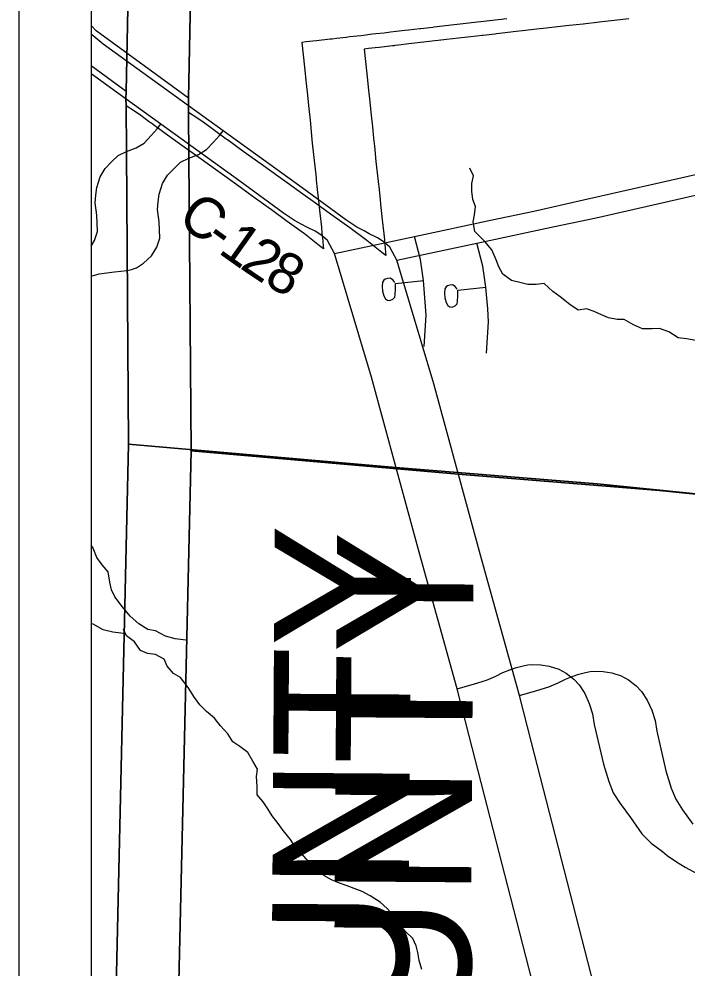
# Model space of a CAD drawing. Extents: x -38.2 to 41.9, y -4 to 24.9.
# Drawn here: x 2 to 2.926, y 15.94 to 17.256 of the extents above; entities that cross this region are included whole.
import ezdxf

# ---------------------------------------------------------------- set-up
doc = ezdxf.new("R2010")
doc.units = 0
for name, color, linetype in [('Default', 7, 'Continuous'), ('GM_X_City_Street', 7, 'Continuous'), ('GM_X_County_Road', 7, 'Continuous'), ('GM_X_County_Road_Text', 7, 'Continuous'), ('GM_X_County_Text', 7, 'Continuous'), ('GM_X_Interchange_Ramps', 7, 'Continuous'), ('GM_X_Interstate_Location', 7, 'Continuous'), ('GM_X_Minor_River', 7, 'Continuous'), ('GM_X_Minor_River_Text', 7, 'Continuous'), ('GM_X_Township_Road_Text', 7, 'Continuous'), ('Level 38', 7, 'Continuous'), ('SH_Cut_Line', 7, 'Continuous'), ('SH_Data', 7, 'Continuous')]:
    doc.layers.add(name, color=color, linetype=linetype)

msp = doc.modelspace()

# ---------------------------------------------------------------- linework, layer by layer
at = {"layer": 'Default'}
msp.add_lwpolyline([(2.6765, 17.2561), (2.6404, 17.252), (2.6356, 17.2515), (2.6158, 17.2492), (2.5991, 17.2473), (2.5955, 17.2469), (2.5756, 17.2446), (2.574, 17.2444), (2.5571, 17.2424), (2.5559, 17.2423), (2.5402, 17.2405), (2.5353, 17.2399), (2.5232, 17.2385), (2.5152, 17.2376), (2.5063, 17.2366), (2.4948, 17.2353), (2.4903, 17.2348), (2.4743, 17.2329), (2.4583, 17.2311), (2.4542, 17.2306), (2.4539, 17.2306), (2.4401, 17.229), (2.4345, 17.2283), (2.4334, 17.2282), (2.4327, 17.2281), (2.4315, 17.228), (2.4128, 17.2258), (2.4074, 17.2252), (2.3982, 17.2242), (2.3923, 17.2235), (2.396, 17.1891), (2.3984, 17.1665), (2.4001, 17.1506), (2.4002, 17.1501), (2.402, 17.1319), (2.4036, 17.1159), (2.4052, 17.0998), (2.4063, 17.0888), (2.4068, 17.0838), (2.4085, 17.0678), (2.4103, 17.0518), (2.412, 17.0358), (2.4123, 17.0328), (2.4137, 17.0198), (2.4154, 17.0038), (2.4172, 16.9868), (2.4193, 16.9672), (2.4202, 16.9589), (2.4206, 16.955), (2.4207, 16.9537), (2.4215, 16.9468), (2.4225, 16.9373), (2.4167, 16.9417), (2.3959, 16.9583), (2.3721, 16.9755), (2.3504, 16.9913), (2.3456, 16.9948), (2.3248, 17.0097), (2.3072, 17.0224), (2.2854, 17.0381), (2.2723, 17.0474), (2.2525, 17.0617), (2.226, 17.0806), (2.2025, 17.0975), (2.201, 17.0986), (2.1827, 17.112), (2.1827, 17.112), (2.1809, 17.1132), (2.1688, 17.1221), (2.1604, 17.1282), (2.1485, 17.1357), (2.1486, 17.1556), (2.1, 17.1909), (2.1, 14.1)], dxfattribs=at)
at = {"layer": 'GM_X_City_Street'}
for points in [[(2.1492, 17.0725), (2.1623, 17.0773), (2.1735, 17.0841), (2.1834, 17.0945), (2.1917, 17.1039), (2.193, 17.1055), (2.1967, 17.1103)], [(2.1, 16.9412), (2.1046, 16.9489), (2.1089, 16.9615), (2.1078, 16.9841), (2.1057, 17.001), (2.1064, 17.0118), (2.1078, 17.0224), (2.1127, 17.0371), (2.1194, 17.0487), (2.1285, 17.0581), (2.1376, 17.0669), (2.1492, 17.0725)], [(2.562, 16.8021), (2.5647, 16.8455), (2.5635, 16.8635), (2.5608, 16.8936), (2.5569, 16.9225), (2.5486, 16.9543)], [(2.5213, 16.8908), (2.5184, 16.8943), (2.5147, 16.8965), (2.5111, 16.8962), (2.5078, 16.8952), (2.5059, 16.894), (2.504, 16.8913), (2.5035, 16.8851), (2.5041, 16.8788), (2.5061, 16.872), (2.5084, 16.8679), (2.5111, 16.8662), (2.5141, 16.8659), (2.5186, 16.8674), (2.521, 16.8703), (2.5218, 16.874), (2.5219, 16.8814), (2.5219, 16.8893), (2.5608, 16.8936)], [(2.6075, 16.3273), (2.6319, 16.3342), (2.6483, 16.3394), (2.6613, 16.3448), (2.6712, 16.3497), (2.6806, 16.3537), (2.69, 16.3568), (2.6993, 16.3593), (2.7055, 16.3604), (2.7114, 16.361), (2.7238, 16.3606), (2.7354, 16.3587), (2.7487, 16.3544), (2.7587, 16.3491), (2.7696, 16.3406), (2.7766, 16.3328), (2.7846, 16.3208), (2.7909, 16.3068), (2.7955, 16.2925), (2.7978, 16.278), (2.8107, 16.223), (2.818, 16.1989), (2.8242, 16.1833), (2.8336, 16.1685), (2.8478, 16.1488), (2.8637, 16.1264), (2.8769, 16.1131), (2.8923, 16.1017), (2.8987, 16.0961), (2.912, 16.0875), (2.9238, 16.0801), (2.958, 16.0613)]]:
    msp.add_lwpolyline(points, dxfattribs=at)
at = {"layer": 'GM_X_County_Road'}
msp.add_line((2.1487, 17.145), (2.1, 17.18), dxfattribs=at)
for points in [[(2.8455, 17.2562), (2.8252, 17.2538), (2.8131, 17.2524), (2.8049, 17.2515), (2.7823, 17.2491), (2.763, 17.2469), (2.7269, 17.2428), (2.722, 17.2423), (2.7022, 17.24), (2.6855, 17.2381), (2.682, 17.2377), (2.662, 17.2354), (2.6605, 17.2352), (2.6436, 17.2333), (2.6424, 17.2331), (2.6266, 17.2313), (2.6218, 17.2307), (2.6097, 17.2294), (2.6017, 17.2284), (2.5928, 17.2274), (2.5813, 17.2261), (2.5768, 17.2256), (2.5608, 17.2237), (2.5448, 17.2219), (2.5407, 17.2214), (2.5404, 17.2214), (2.5265, 17.2198), (2.521, 17.2192), (2.5199, 17.219), (2.5191, 17.2189), (2.518, 17.2188), (2.4993, 17.2167), (2.4939, 17.216), (2.4847, 17.215), (2.4788, 17.2143), (2.4825, 17.1799), (2.4849, 17.1573), (2.4866, 17.1414), (2.4867, 17.1409), (2.4885, 17.1227), (2.4901, 17.1067), (2.4917, 17.0906), (2.4928, 17.0796), (2.4933, 17.0746), (2.495, 17.0586), (2.4967, 17.0426), (2.4985, 17.0266), (2.4988, 17.0236), (2.5002, 17.0106), (2.5019, 16.9946), (2.5037, 16.9776), (2.5058, 16.9581), (2.5067, 16.9497), (2.5071, 16.9458), (2.5072, 16.9445), (2.5079, 16.9376), (2.5089, 16.9281), (2.5032, 16.9325), (2.4824, 16.9491), (2.4586, 16.9663), (2.4368, 16.9821), (2.4321, 16.9856), (2.4113, 17.0005), (2.3937, 17.0132), (2.3718, 17.0289), (2.3588, 17.0382), (2.3389, 17.0525), (2.3125, 17.0715), (2.289, 17.0883), (2.2874, 17.0894), (2.2692, 17.1028), (2.2692, 17.1028), (2.2674, 17.1041), (2.2553, 17.1129), (2.2468, 17.119), (2.235, 17.1266), (2.2351, 17.1464), (2.1069, 17.2395), (2.1, 17.2471), (2.1, 14.1)], [(2.4207, 16.9551), (2.42, 16.9557), (2.4109, 16.9618), (2.3993, 16.9675), (2.3921, 16.9713), (2.3821, 16.9766), (2.3667, 16.987), (2.3064, 17.0312), (2.1967, 17.1103), (2.1487, 17.145)], [(2.4376, 16.9307), (2.5486, 16.9543), (2.6562, 16.9777), (2.7139, 16.9895), (2.7828, 17.0054), (2.9953, 17.0536), (3.0911, 17.077), (3.0948, 17.0781)], [(2.4376, 16.9307), (2.4278, 16.9487), (2.4207, 16.9551)], [(2.523, 16.6337), (2.4888, 16.7592), (2.4376, 16.9307)], [(2.8235, 15.1398), (2.8339, 15.2041), (2.8358, 15.2222), (2.8341, 15.2358), (2.8313, 15.2481), (2.7757, 15.4503), (2.7392, 15.5699), (2.7209, 15.6326), (2.7183, 15.6447), (2.7166, 15.6563), (2.7158, 15.6686), (2.7163, 15.6779), (2.7246, 15.7195), (2.7319, 15.7477), (2.7392, 15.7855), (2.7397, 15.7991), (2.7385, 15.818), (2.7355, 15.8321), (2.7196, 15.8918), (2.6244, 16.262), (2.6075, 16.3273), (2.5551, 16.5169), (2.523, 16.6337)]]:
    msp.add_lwpolyline(points, dxfattribs=at)
at = {"layer": 'GM_X_Interchange_Ramps'}
for points in [[(2.1, 20.4515), (2.1, 14.1636), (2.1303, 14.1626), (2.1303, 14.1722), (2.1335, 15.4167), (2.1334, 15.4951), (2.1328, 15.831), (2.1521, 16.6664), (2.1489, 17.073), (2.1485, 17.1357), (2.1484, 17.1455), (2.1486, 17.1556), (2.1569, 17.5704), (2.1549, 17.5972), (2.1521, 17.6416), (2.1422, 17.7563), (2.1427, 17.838), (2.1429, 18.1709), (2.1421, 18.2952), (2.138, 18.8976), (2.1339, 19.396), (2.1223, 20.2725), (2.1124, 20.4526)], [(2.1, 20.4344), (2.1, 14.1575), (2.2168, 14.1534), (2.2168, 14.163), (2.22, 15.4075), (2.2199, 15.4859), (2.2193, 15.8218), (2.2386, 16.6572), (2.2354, 17.0638), (2.235, 17.1266), (2.2349, 17.1363), (2.2351, 17.1464), (2.2434, 17.5612), (2.2414, 17.5881), (2.2386, 17.6324), (2.2287, 17.7471), (2.2291, 17.8288), (2.2294, 18.1617), (2.2286, 18.286), (2.2245, 18.8884), (2.2204, 19.3868), (2.2088, 20.2633), (2.1989, 20.4434)]]:
    msp.add_lwpolyline(points, close=True, dxfattribs=at)
for points in [[(2.1569, 17.5704), (2.1486, 17.1556), (2.1484, 17.1455), (2.1485, 17.1357), (2.1489, 17.073), (2.1521, 16.6664), (2.5228, 16.6342), (2.8019, 16.6115), (3.0621, 16.5852), (3.1389, 16.5821), (3.471, 16.5538), (3.8743, 16.4969), (3.8908, 16.5049), (3.9086, 16.5077), (3.9238, 16.5054), (3.9778, 16.5019), (4.1257, 16.4908), (4.1951, 16.4857), (4.2738, 16.48), (4.4315, 16.4679)], [(2.2434, 17.5612), (2.2351, 17.1464), (2.2349, 17.1363), (2.235, 17.1266), (2.2354, 17.0638), (2.2386, 16.6572), (2.6092, 16.625), (2.8884, 16.6024), (3.1485, 16.5761), (3.2254, 16.5729), (3.5575, 16.5447), (3.9608, 16.4877), (3.9773, 16.4958), (3.9951, 16.4985), (4.0103, 16.4962), (4.0643, 16.4927), (4.2121, 16.4816), (4.2816, 16.4765), (4.3603, 16.4708)], [(4.4315, 16.4679), (4.2738, 16.48), (4.1951, 16.4857), (4.1257, 16.4908), (3.9778, 16.5019), (3.9238, 16.5054), (3.9086, 16.5077), (3.8908, 16.5049), (3.8743, 16.4969), (3.471, 16.5538), (3.1389, 16.5821), (3.0621, 16.5852), (2.8019, 16.6115), (2.5228, 16.6342), (2.1521, 16.6664), (2.1328, 15.831), (2.1334, 15.4951), (2.1335, 15.4167), (2.1303, 14.1722), (2.1303, 14.1626), (2.1, 14.1636), (2.1, 14.1), (6.3126, 14.1)], [(4.3603, 16.4708), (4.2816, 16.4765), (4.2121, 16.4816), (4.0643, 16.4927), (4.0103, 16.4962), (3.9951, 16.4985), (3.9773, 16.4958), (3.9608, 16.4877), (3.5575, 16.5447), (3.2254, 16.5729), (3.1485, 16.5761), (2.8884, 16.6024), (2.6092, 16.625), (2.2386, 16.6572), (2.2193, 15.8218), (2.2199, 15.4859), (2.22, 15.4075), (2.2168, 14.163), (2.2168, 14.1534), (2.1, 14.1575), (2.1, 14.1), (6.3995, 14.1)]]:
    msp.add_lwpolyline(points, dxfattribs=at)
at = {"layer": 'GM_X_Interstate_Location'}
for points in [[(2.2356, 17.0633), (2.2488, 17.0682), (2.26, 17.0749), (2.2699, 17.0853), (2.2782, 17.0947), (2.2794, 17.0963), (2.2832, 17.1012)], [(2.1559, 16.9089), (2.1631, 16.911), (2.1725, 16.9176), (2.1838, 16.9275), (2.1911, 16.9397), (2.1953, 16.9523), (2.1943, 16.975), (2.1922, 16.9918), (2.1929, 17.0027), (2.1943, 17.0132), (2.1992, 17.0279), (2.2058, 17.0395), (2.215, 17.0489), (2.2241, 17.0577), (2.2356, 17.0633)], [(2.6485, 16.7929), (2.6512, 16.8363), (2.65, 16.8543), (2.6473, 16.8844), (2.6434, 16.9133), (2.6351, 16.9451)], [(2.1, 16.8994), (2.1112, 16.9029), (2.1326, 16.9054), (2.1498, 16.9071), (2.1559, 16.9089)], [(2.6078, 16.8816), (2.6049, 16.8851), (2.6012, 16.8873), (2.5976, 16.887), (2.5943, 16.886), (2.5924, 16.8848), (2.5905, 16.8821), (2.59, 16.8759), (2.5906, 16.8696), (2.5926, 16.8628), (2.5948, 16.8587), (2.5976, 16.857), (2.6006, 16.8567), (2.6051, 16.8583), (2.6075, 16.8611), (2.6083, 16.8649), (2.6084, 16.8722), (2.6084, 16.8801), (2.6473, 16.8844)], [(2.694, 16.3181), (2.7183, 16.325), (2.7348, 16.3302), (2.7478, 16.3356), (2.7577, 16.3405), (2.7671, 16.3445), (2.7765, 16.3476), (2.7858, 16.3501), (2.792, 16.3513), (2.7979, 16.3518), (2.8102, 16.3514), (2.8219, 16.3495), (2.8351, 16.3452), (2.8451, 16.3399), (2.856, 16.3314), (2.8631, 16.3236), (2.8711, 16.3116), (2.8774, 16.2976), (2.882, 16.2834), (2.8843, 16.2688), (2.8971, 16.2138), (2.9045, 16.1897), (2.9107, 16.1741), (2.9201, 16.1593), (2.9343, 16.1396)]]:
    msp.add_lwpolyline(points, dxfattribs=at)
at = {"layer": 'GM_X_Minor_River'}
for points in [[(2.9385, 16.8103), (2.9256, 16.8126), (2.9143, 16.8138), (2.901, 16.8225), (2.8881, 16.8267), (2.8782, 16.8264), (2.8646, 16.8264), (2.8524, 16.8322), (2.8391, 16.8394), (2.8293, 16.8395), (2.8175, 16.8418), (2.8077, 16.846), (2.7974, 16.8506), (2.7868, 16.854), (2.7754, 16.8521), (2.7637, 16.8601), (2.7504, 16.8708), (2.7402, 16.8781), (2.7281, 16.8891), (2.7174, 16.888), (2.7056, 16.888), (2.6962, 16.8903), (2.6829, 16.8934), (2.6708, 16.9022), (2.6655, 16.9125), (2.6617, 16.9223), (2.6557, 16.936), (2.6458, 16.9475), (2.6322, 16.9615), (2.63, 16.9748), (2.6319, 16.9843), (2.6331, 16.9961), (2.6293, 17.006), (2.6278, 17.0174), (2.6278, 17.028), (2.6305, 17.0386), (2.6252, 17.0493)], [(2.1448, 16.4039), (2.13, 16.4058), (2.1167, 16.4093), (2.1031, 16.4169), (2.1, 16.4174)], [(2.5587, 15.9382), (2.5548, 15.9505), (2.5532, 15.9616), (2.5508, 15.9711), (2.5461, 15.9811), (2.5361, 15.9909), (2.5273, 16.0014), (2.52, 16.0126), (2.5104, 16.0227), (2.5008, 16.0314), (2.4869, 16.0401), (2.4761, 16.0461), (2.4648, 16.0502), (2.4551, 16.0542), (2.4445, 16.0576), (2.4333, 16.0624), (2.4228, 16.0684), (2.4113, 16.0794), (2.4009, 16.0884), (2.3921, 16.0985), (2.3832, 16.1082), (2.3763, 16.1183), (2.3663, 16.1307), (2.3594, 16.1404), (2.3513, 16.1513), (2.3451, 16.1609), (2.3385, 16.1706), (2.3304, 16.1803), (2.3304, 16.1917), (2.3296, 16.2055), (2.3306, 16.2161), (2.3244, 16.2269), (2.3172, 16.2389), (2.3064, 16.2471), (2.2967, 16.2538), (2.2897, 16.2647), (2.2794, 16.276), (2.2713, 16.2868), (2.2602, 16.2959), (2.2506, 16.3049), (2.2436, 16.3153), (2.2345, 16.3289), (2.2242, 16.3428), (2.2145, 16.3484), (2.2057, 16.3589), (2.2014, 16.3685), (2.1894, 16.3749), (2.1784, 16.3763), (2.1687, 16.3804), (2.1602, 16.3924), (2.1491, 16.4007), (2.1448, 16.4098)]]:
    msp.add_lwpolyline(points, dxfattribs=at)
at = {"layer": 'GM_X_Minor_River_Text'}
msp.add_lwpolyline([(2.2312, 16.3947), (2.2165, 16.3966), (2.2032, 16.4001), (2.1895, 16.4077), (2.1789, 16.4096), (2.1664, 16.4176), (2.1543, 16.4279), (2.1429, 16.4416), (2.1331, 16.4549), (2.1285, 16.4644), (2.1259, 16.475), (2.1237, 16.4895), (2.1153, 16.4994), (2.1078, 16.5092), (2.1028, 16.5222), (2.1, 16.5266)], dxfattribs=at)
at = {"layer": 'GM_X_Township_Road_Text'}
for points in [[(2.2351, 17.1358), (2.1166, 17.2211), (2.1, 17.2352)], [(2.5072, 16.9459), (2.5065, 16.9465), (2.4974, 16.9526), (2.4858, 16.9583), (2.4786, 16.9621), (2.4686, 16.9674), (2.4532, 16.9778), (2.3929, 17.022), (2.2832, 17.1012), (2.2351, 17.1358)], [(2.5241, 16.9215), (2.6351, 16.9451), (2.7427, 16.9685), (2.8004, 16.9803), (2.8693, 16.9962), (3.0818, 17.0445), (3.1776, 17.0678), (3.1813, 17.0689)], [(2.5241, 16.9215), (2.5143, 16.9395), (2.5072, 16.9459)], [(2.6095, 16.6245), (2.5753, 16.7501), (2.5241, 16.9215)], [(2.91, 15.1306), (2.9204, 15.1949), (2.9223, 15.213), (2.9206, 15.2266), (2.9178, 15.2389), (2.8622, 15.4411), (2.8256, 15.5607), (2.8073, 15.6234), (2.8048, 15.6355), (2.8031, 15.6471), (2.8023, 15.6594), (2.8028, 15.6687), (2.8111, 15.7103), (2.8184, 15.7385), (2.8257, 15.7763), (2.8262, 15.7899), (2.825, 15.8088), (2.8219, 15.8229), (2.8061, 15.8826), (2.7109, 16.2528), (2.694, 16.3181), (2.6416, 16.5077), (2.6095, 16.6245)]]:
    msp.add_lwpolyline(points, dxfattribs=at)
at = {"layer": 'SH_Cut_Line'}
msp.add_lwpolyline([(2.1103, 20.9), (2.1, 20.9), (2.1, 14.1636), (2.1303, 14.1626), (2.1303, 14.1722), (2.1335, 15.4167), (2.1334, 15.4951), (2.1328, 15.831), (2.1521, 16.6664), (2.1489, 17.073), (2.1485, 17.1357), (2.1484, 17.1455), (2.1486, 17.1556), (2.1569, 17.5704), (2.1549, 17.5972), (2.1521, 17.6416), (2.1422, 17.7563), (2.1427, 17.838), (2.1429, 18.1709), (2.1421, 18.2952), (2.138, 18.8976), (2.1339, 19.396), (2.1223, 20.2725), (2.1124, 20.4526)], close=True, dxfattribs=at)
for points in [[(2.1569, 17.5704), (2.1486, 17.1556), (2.1484, 17.1455), (2.1485, 17.1357), (2.1489, 17.073), (2.1521, 16.6664), (2.5228, 16.6342), (2.8019, 16.6115), (3.0621, 16.5852), (3.1389, 16.5821), (3.471, 16.5538), (3.8743, 16.4969), (3.8908, 16.5049), (3.9086, 16.5077), (3.9238, 16.5054), (3.9778, 16.5019), (4.1257, 16.4908), (4.1951, 16.4857), (4.2738, 16.48), (4.4315, 16.4679)], [(4.4315, 16.4679), (4.2738, 16.48), (4.1951, 16.4857), (4.1257, 16.4908), (3.9778, 16.5019), (3.9238, 16.5054), (3.9086, 16.5077), (3.8908, 16.5049), (3.8743, 16.4969), (3.471, 16.5538), (3.1389, 16.5821), (3.0621, 16.5852), (2.8019, 16.6115), (2.5228, 16.6342), (2.1521, 16.6664), (2.1328, 15.831), (2.1334, 15.4951), (2.1335, 15.4167), (2.1303, 14.1722), (2.1303, 14.1626), (2.1, 14.1636), (2.1, 14.1), (8.9, 14.1)]]:
    msp.add_lwpolyline(points, dxfattribs=at)
at = {"layer": 'SH_Data'}
for p, q in [((2, 21), (2, 14)), ((2.1, 20.9), (2.1, 14.1))]:
    msp.add_line(p, q, dxfattribs=at)

# ---------------------------------------------------------------- texts
at = {"layer": 'GM_X_County_Road_Text'}
for s, rotation, p in [('C', 323.8053, (2.2176, 16.9744)), ('-', 324.0083, (2.2554, 16.9467)), ('1', 324.6579, (2.2748, 16.9326)), ('2', 326.2342, (2.3048, 16.9114)), ('8', 330.4704, (2.3378, 16.8895))]:
    msp.add_text(s, height=0.0568, rotation=rotation, dxfattribs=at).set_placement(p)
at = {"layer": 'GM_X_County_Text'}
msp.add_text('FRANKLIN COUNTY', height=0.189394, rotation=89.6111, dxfattribs=at).set_placement((2.5279, 14.1618))
at = {"layer": 'Level 38'}
msp.add_text('FRANKLIN COUNTY', height=0.189394, rotation=89.6111, dxfattribs=at).set_placement((2.6144, 14.1526))

doc.saveas('drawing.dxf')
